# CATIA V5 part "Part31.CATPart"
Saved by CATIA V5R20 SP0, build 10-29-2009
Part number: socket countersunk head screw_din_DIN 7991 - M8 x 20 --- 20N
Revision: ANY
Definition: UNKNOWN
Nomenclature: socket countersunk head screw_din_DIN 7991 - M8 x 20 --- 20N
Source: Unknown
Bounding box of the stored display mesh (mm): x 0 to 20, y -7.59 to 7.59, z -7.785 to 7.785
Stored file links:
  C:\Users\Utente\Desktop\IO LAVORO\3D X SITO CF\CUMSA\3D files GR\GR 424546-15\Part31.CATPart
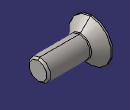
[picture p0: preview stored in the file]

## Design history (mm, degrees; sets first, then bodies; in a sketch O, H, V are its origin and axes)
Body1 "Hex" (main body)
  Solid1: solid without history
